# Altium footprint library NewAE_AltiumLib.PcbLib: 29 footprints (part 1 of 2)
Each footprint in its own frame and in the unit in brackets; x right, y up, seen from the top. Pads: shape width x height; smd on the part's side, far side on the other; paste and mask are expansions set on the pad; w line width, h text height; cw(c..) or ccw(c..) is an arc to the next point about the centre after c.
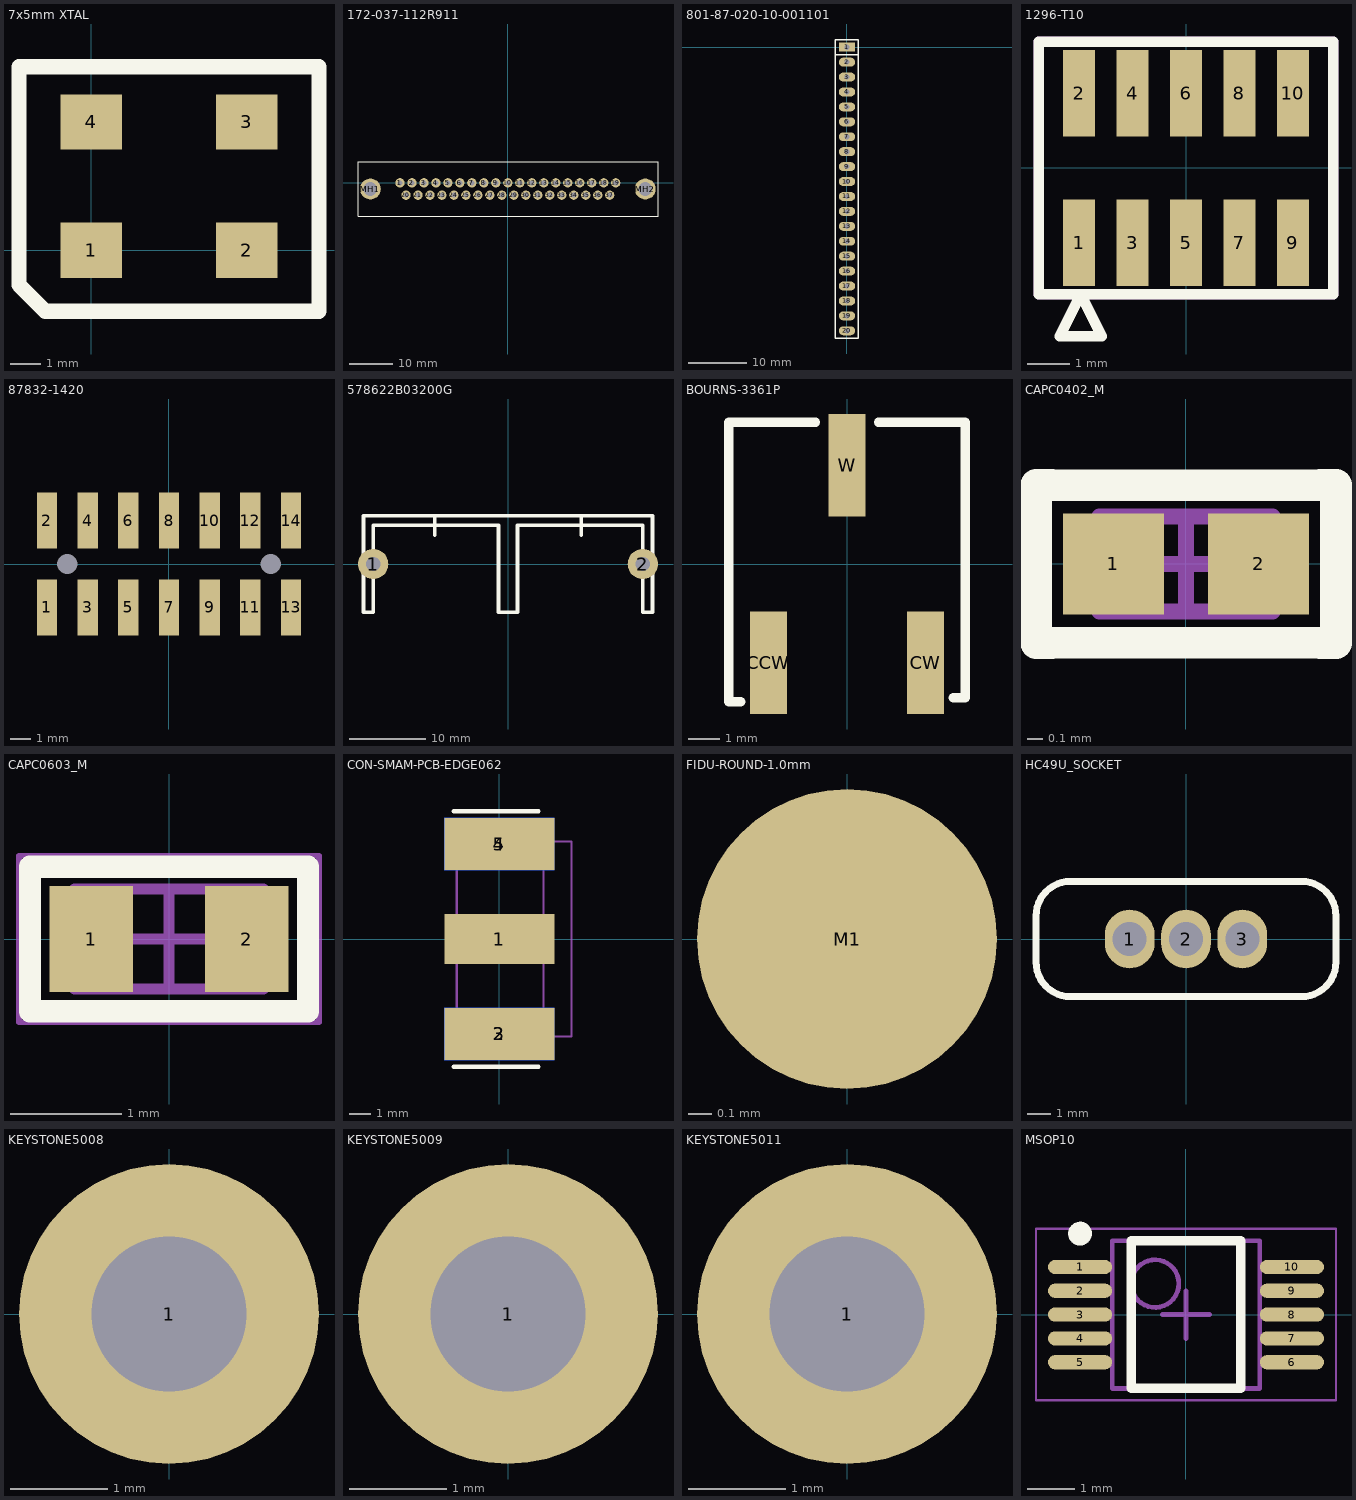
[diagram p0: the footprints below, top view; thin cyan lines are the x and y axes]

## 7x5mm XTAL [mil]
pads (4):
  rect 79x71 smd: 1(0,0) 2(200,0) 3(200,165) 4(0,165)
Top Overlay:
  lines w19.68: -93,79 -93,236.22 275.59,236.22 ; -93,86 -93,-44.8 -59.06,-78.74 293,-78.74 293,86 ; 279,236.22 293,236.22 293,79
3D body: height 70.87, standoff 0, extent -39.37,-39.37 236.22,196.85

## 172-037-112R911 [mil] "DB37 Male Header Board Mount"
pads (39):
  round 85 / inner round 70 / far side round 85 hole 47 unplated: 1(-981,0) 2(-872,0) 3(-763,0) 4(-654,0) 5(-545,0) 6(-436,0) 7(-327,0) 8(-218,0) 9(-109,0) 10(0,0) 11(109,0) 12(218,0) 13(327,0) 14(436,0) 15(545,0) 16(654,0) 17(763,0) 18(872,0) 19(981,0) 20(-926.5,-112) 21(-817.5,-112) 22(-708.5,-112) 23(-599.5,-112) 24(-490.5,-112) 25(-381.5,-112) 26(-272.5,-112) 27(-163.5,-112) 28(-54.5,-112) 29(54.5,-112) 30(163.5,-112) 31(272.5,-112) 32(381.5,-112) 33(490.5,-112) 34(599.5,-112) 35(708.5,-112) 36(817.5,-112) 37(926.5,-112)
  round 190 hole 123 unplated: MH1(-1250,-56) MH2(1250,-56)
Top Overlay:
  lines w10: -1362.52,-303.99 -1362.52,192.01 1365.48,192.01 1365.48,-303.99 -1362.52,-303.99
3D body "172-037-112.STEP": height 494.5, standoff -189, extent -1362.52,-303.99 1365.48,192.01

## 801-87-020-10-001101 [mil]
pads (20):
  rect 110x60 hole 35: 1(0,0)
  oval 110x60 hole 35: 2(0,-100) 3(0,-200) 4(0,-300) 5(0,-400) 6(0,-500) 7(0,-600) 8(0,-700) 9(0,-800) 10(0,-900) 11(0,-1000) 12(0,-1100) 13(0,-1200) 14(0,-1300) 15(0,-1400) 16(0,-1500) 17(0,-1600) 18(0,-1700) 19(0,-1800) 20(0,-1900)
Top Overlay:
  lines w10: -78.74,-50 78.74,-50 ; -78.74,-1950 -78.74,50 75,50 75,-1950 -78.74,-1950
3D body "pcb_connector_801-87-020-10-268101.stp": height 224.45, standoff 0, extent -50,-1950 50,50

## 1296-T10 [mm] "1.27mm x 10-pin"
height 4.5
pads (10):
  rect 0.76x2.05 smd: 1(-2.54,-1.775) 2(-2.54,1.775) 3(-1.27,-1.775) 4(-1.27,1.775) 5(0,-1.775) 6(0,1.775) 7(1.27,-1.775) 8(1.27,1.775) 9(2.54,-1.775) 10(2.54,1.775)
Top Overlay:
  lines w0.254: -3.5,-3 3.5,-3 3.5,3 -3.5,3 -3.5,-3 ; -3,-4 -2.5,-3 -2,-4 -3,-4
Top 3D:
  lines w0.254: -3.5,-3 3.5,-3 3.5,3 -3.5,3 -3.5,-3
Top Courtyard:
  lines w0.254: -3.5,-3 3.5,-3 3.5,3 -3.5,3 -3.5,-3

## 87832-1420 [mm] "87832-1420 (Molex)"
height 12
pads (16):
  rect 1x2.75 smd: 1(-6,-2.13) 2(-6,2.13) 3(-4,-2.13) 4(-4,2.13) 5(-2,-2.13) 6(-2,2.13) 7(0,-2.13) 8(0,2.13) 9(2,-2.13) 10(2,2.13) 11(4,-2.13) 12(4,2.13) 13(6,-2.13) 14(6,2.13)
  round 0 hole 1 unplated: MH1(-5,0) MH2(5,0)
3D body "878321420.stp": height 7.58, standoff -0.77, extent -8.325,-3.15 8.325,3.15

## 578622B03200G [mm] "Aavid Dual TO220 Heatsink 578622B03200G"
pads (2):
  round 4 hole 1.91 unplated: 1(-17.78,0) 2(17.78,0)
Top Overlay:
  lines w0.5: -9.65,3.81 -9.65,6.35 ; 9.65,3.81 9.65,6.35 ; -19.05,-6.35 -19.05,6.35 19.05,6.35 19.05,-6.35 17.78,-6.35 17.78,5.105 8.23,5.105 1.27,5.105 1.27,-6.35 -1.27,-6.35 -1.27,5.105 -10.87,5.105 -17.78,5.105 -17.78,-6.35 -19.05,-6.35

## BOURNS-3361P [mil]
pads (3):
  rect 47x130 smd: CCW(-100,-125.5) CW(100,-125.5) W(0,125.5)
Top Overlay:
  lines w12: -135,-175 -150,-175 -150,180 -40,180 ; 40,180 150,180 150,-170 135,-170
3D body "3361p001.stp": height 206, standoff 0, extent -133,-165 131,171

## CAPC0402_M [mm] "Chip Capacitor, 2-Leads, Body 0402, IPC Medium Density"
height 0.6
pads (2):
  rect 0.64x0.64 smd: 1(-0.46,0) 2(0.46,0)
Top Overlay:
  lines w0.2: -0.85,-0.5 0.85,-0.5 ; -0.85,0.5 0.85,0.5
  lines w0.203: -0.85,-0.5 -0.95,-0.5 -0.95,0.5 -0.85,0.5 ; 0.85,-0.5 0.95,-0.5 0.95,0.5 0.85,0.5
Top 3D:
  lines w0.1: -0.55,-0.3 0.55,-0.3 0.55,0.3 -0.55,0.3 -0.55,-0.3
Top Courtyard:
  lines w0.05: -0.95,-0.5 0.95,-0.5 0.95,0.5 -0.95,0.5 -0.95,-0.5
  lines w0.1: -0.3,0 0.3,0 ; 0,-0.3 0,0.3
3D body "CAPC0402_M.step": height 0.6, standoff 0, extent -0.55,-0.3 0.55,0.3

## CAPC0603_M [mm]
height 0.9
pads (2):
  rect 0.75x0.95 smd: 1(-0.7,0) 2(0.7,0)
Top Overlay:
  lines w0.2: -1.25,-0.65 -1.1,-0.65 1.1,-0.65 1.25,-0.65 1.25,0.65 1.1,0.65 -1.1,0.65 -1.25,0.65 -1.25,-0.65
Top 3D:
  lines w0.1: -0.85,-0.45 -0.85,0.45 0.85,0.45 0.85,-0.45 -0.85,-0.45
Top Courtyard:
  lines w0.05: -1.35,-0.75 -1.35,0.75 1.35,0.75 1.35,-0.75 -1.35,-0.75
  lines w0.1: -0.45,0 0.45,0 ; 0,-0.45 0,0.45
3D body "CAPC0603_M.step": height 0.9, standoff 0, extent -0.85,-0.45 0.85,0.45

## CON-SMAM-PCB-EDGE062 [mm] "Connector, SMA Edge Mount for 0.062\" Thick Board, 5-Lead"
height 4.78
pads (5):
  rect 5.08x2.29 smd: 1(0,0)
  rect 5.08x2.415 smd: 2(0,-4.383) 5(0,4.383)
  rect 5.08x2.415 smd far side: 3(0,-4.383) 4(0,4.383)
Top Overlay:
  lines w0.2: -2.1,-5.9 1.8,-5.9 ; -2.1,5.9 1.8,5.9
Bottom Overlay:
  lines w0.2: -2.1,-5.9 1.8,-5.9 ; -2.1,5.9 1.8,5.9
Top 3D:
  lines w0.1: 2.032,-3.25 -1.968,-3.25 -1.968,3.25 2.032,3.25 ; 2.032,-4.5 2.032,4.5 3.332,4.5 3.332,-4.5 2.032,-4.5
Top Courtyard:
  lines w0.1: -0.5,0 0.5,0 ; 0,-0.5 0,0.5
3D body "3d_sma.stp": height 4.34, standoff -3.58, extent -2.15,-4.8 15.3,4.72

## FIDU-ROUND-1.0mm [mm]
pads (1):
  round 1.27 smd paste-2 mask+0.7: M1(0,0)

## HC49U_SOCKET [mil] "3x 0667-0-15-15-30-27-10-0"
pads (3):
  oval 85x100 hole 58: 1(-96.06,0) 2(0,0) 3(96.06,0)
Top Overlay:
  lines w11.81: -255.91,-39.37 ccw(c-196.85,-39.37) -196.85,-98.43 196.85,-98.43 ccw(c196.85,-39.37) 255.91,-39.37 255.91,39.37 ccw(c196.85,39.37) 196.85,98.43 -196.85,98.43 ccw(c-196.85,39.37) -255.91,39.37 -255.91,-39.37
3D body "mill-max-0667-0-15-15-30-XX-10-0.step": height 16, standoff -145, extent -132.06,-35.99 -60.06,36.01
3D body "mill-max-0667-0-15-15-30-XX-10-0.step": height 16, standoff -145, extent -35.99,-35.99 36.01,36.01
3D body "mill-max-0667-0-15-15-30-XX-10-0.step": height 16, standoff -145, extent 60.07,-35.99 132.07,36.01

## KEYSTONE5008 [mm] "TEST POINT PC MULTI PURPOSE ORG"
pads (1):
  round 3.1 hole 1.6: 1(0,0)
3D body "keystone-PN5008.STEP": height 5.47, standoff -3.44, extent -1.587,-1.587 1.588,1.588

## KEYSTONE5009 [mm] "TEST POINT PC MULTI PURPOSE YEL"
pads (1):
  round 3.1 hole 1.6: 1(0,0)
3D body "keystone-PN5009.STEP": height 5.47, standoff -3.44, extent -1.587,-1.587 1.588,1.588

## KEYSTONE5011 [mm] "TEST POINT PC MULTI PURPOSE BLK"
pads (1):
  round 3.1 hole 1.6: 1(0,0)
3D body "keystone-PN5011.STEP": height 8.13, standoff -3.17, extent -1.587,-1.587 1.587,1.587

## MSOP10 [mm] "0.5mm pitch MSOP10 / MO-187"
height 1.1
pads (10):
  oval 1.35x0.3 smd: 1(-2.225,1) 2(-2.225,0.5) 3(-2.225,0) 4(-2.225,-0.5) 5(-2.225,-1) 6(2.225,-1) 7(2.225,-0.5) 8(2.225,0) 9(2.225,0.5) 10(2.225,1)
Top Overlay:
  circle w0.25: c-2.225,1.7 r0.125
  lines w0.2: -1.15,-1.55 -1.15,1.55 1.15,1.55 1.15,-1.55 -1.15,-1.55
Top 3D:
  circle w0.1: c-0.65,0.65 r0.5
  lines w0.1: -1.55,-1.55 -1.55,1.55 1.55,1.55 1.55,-1.55 -1.55,-1.55
Top Courtyard:
  lines w0.05: -3.15,-1.8 -3.15,1.8 3.15,1.8 3.15,-1.8 -3.15,-1.8
  lines w0.1: -0.5,0 0.5,0 ; 0,-0.5 0,0.5
3D body "MSOP10-MO-187.step": height 1.1, standoff 0, extent -2.442,-1.55 2.442,1.55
